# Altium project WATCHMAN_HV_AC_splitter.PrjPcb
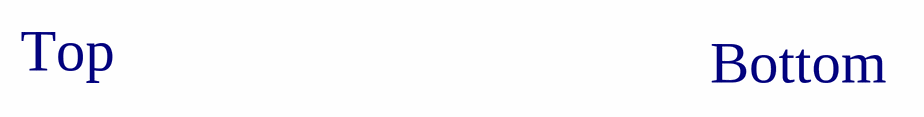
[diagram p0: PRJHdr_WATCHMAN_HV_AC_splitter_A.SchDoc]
Approved_By: Gary S. Varner; BoardName: WATCHMAN HV AC splitter; Designer: Jose Duron; Drawn_By: Jose Duron; IDLnum: IDL_18_045; ProjectName1: WATCHMAN HV AC splitter; RevNum: A
2 sheets, 14 parts. Net scope: global (net labels, ports and power ports of the same name join across sheets).
Board file: WATCHMAN_HV_AC_splitter.PcbDoc
Sheets:
  PRJHdr_WATCHMAN_HV_AC_splitter_A.SchDoc
  HV_AC_splitter.SchDoc

## Sheet PRJHdr_WATCHMAN_HV_AC_splitter_A.SchDoc: Title_doc_parameter!
size 401 x 291 mm; DocumentNumber: 1; SheetNumber: 1; SheetTotal: 2; Project_IT-Code: XXXX

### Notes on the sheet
- Top
- Bottom

## Sheet HV_AC_splitter.SchDoc: '
size 401 x 291 mm; DocumentNumber: 2; SheetNumber: 2; SheetTotal: 2
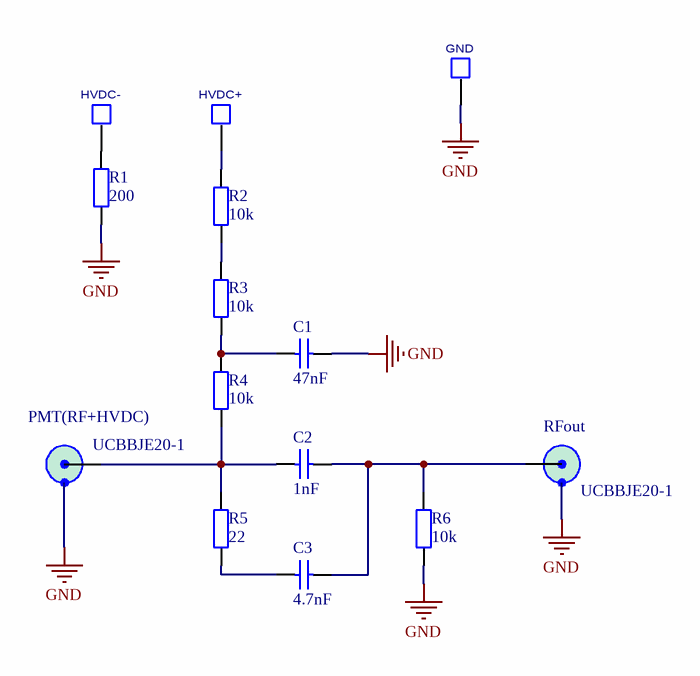
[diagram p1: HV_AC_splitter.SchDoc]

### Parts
C1  47nF  [CAPNQR7.5-3X10X8.5]
C2  1nF  [CAPNQR7.5-3X10X8.5]
C3  4.7nF  [CAPNQR7.5-3X10X8.5]
GND  TEST-POINT-SURFACE-MOUNT  [TPH0.5S]  (value not drawn)
HVDC+  TEST-POINT-SURFACE-MOUNT  [TPH0.5S]  (value not drawn)
HVDC-  TEST-POINT-SURFACE-MOUNT  [TPH0.5S]  (value not drawn)
PMT(RF+HVDC)  UCBBJE20-1  [UCBBJE20-1]
R1  200  [CC1206N1R]
R2  10k  [CC1206N1R]
R3  10k  [CC1206N1R]
R4  10k  [CC1206N1R]
R5  22  [CC1206N1R]
R6  10k  [CC1206N1R]
RFout  UCBBJE20-1  [UCBBJE20-1]

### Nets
GND: C1.2 GND.1 PMT(RF+HVDC).2 R1.1 R6.1 RFout.2
NetC1_1: C1.1 R3.1 R4.2
NetC2_1: C2.1 PMT(RF+HVDC).1 R4.1 R5.2
NetC2_2: C2.2 C3.2 R6.2 RFout.1
NetC3_1: C3.1 R5.1
NetHVDC+_1: HVDC+.1 R2.2
NetHVDC-_1: HVDC-.1 R1.2
NetR2_1: R2.1 R3.2

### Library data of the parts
C1-C3 = CAPCC1206_100N200VX7R: Capacitor chip ceramic 1206; Manufacturer: Kemet, Farnell; Manufacturer No: C1206C106K8RAC , 1288264; Comment2: 200V X7R 10%; Sort: 210; Tech: SMDR
PMT(RF+HVDC) RFout = UCBBJE20-1: 75R Circuit Board Bulkhead Edge Mount  Coax “BNC” Style Receptacle; Manufacturer: Trompeter; Sort: 610; Tech: THDW
R1-R6 = RES1206: Chip Resistor 1206; Comment2: 0.25W 1% 200ppm; Sort: 110; Tech: SMDR

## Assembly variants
Single-Ended Input: not fitted C2 C4 C9 C10 C19 C20 C22 C24 C29 C30 C39 C40 C42 C45 C50 C52 C54 C59 C60 C69 C70 C72 C74 C79 C80 C89 C90 C92 C95 C100 C102 C104 C109 C110 C119 C120 C122 C124 C129 C130 C139 C140 C142 C145 C150 HS1 R3 R5 R7 R23 R25 R39 R50 R52 R68 R70 R84 R95 R97 R113 R115 R129 R164 R165 R166 R167 R168 R169 R170 R171 R172 R173 R174 R175 R176 R177 R178 TIP1
Differential Input: not fitted C2 C4 C19 C20 C22 C24 C39 C40 C42 C50 C52 C54 C69 C70 C72 C74 C89 C90 C92 C100 C102 C104 C119 C120 C122 C124 C139 C140 C142 C150 HS1 R4 R5 R7 R13 R14 R21 R22 R23 R25 R31 R32 R38 R39 R48 R49 R50 R52 R58 R59 R66 R67 R68 R70 R76 R77 R83 R84 R88 R93 R94 R95 R97 R103 R104 R111 R112 R113 R115 R121 R122 R128 R129 R133 R164 R333 TIP1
